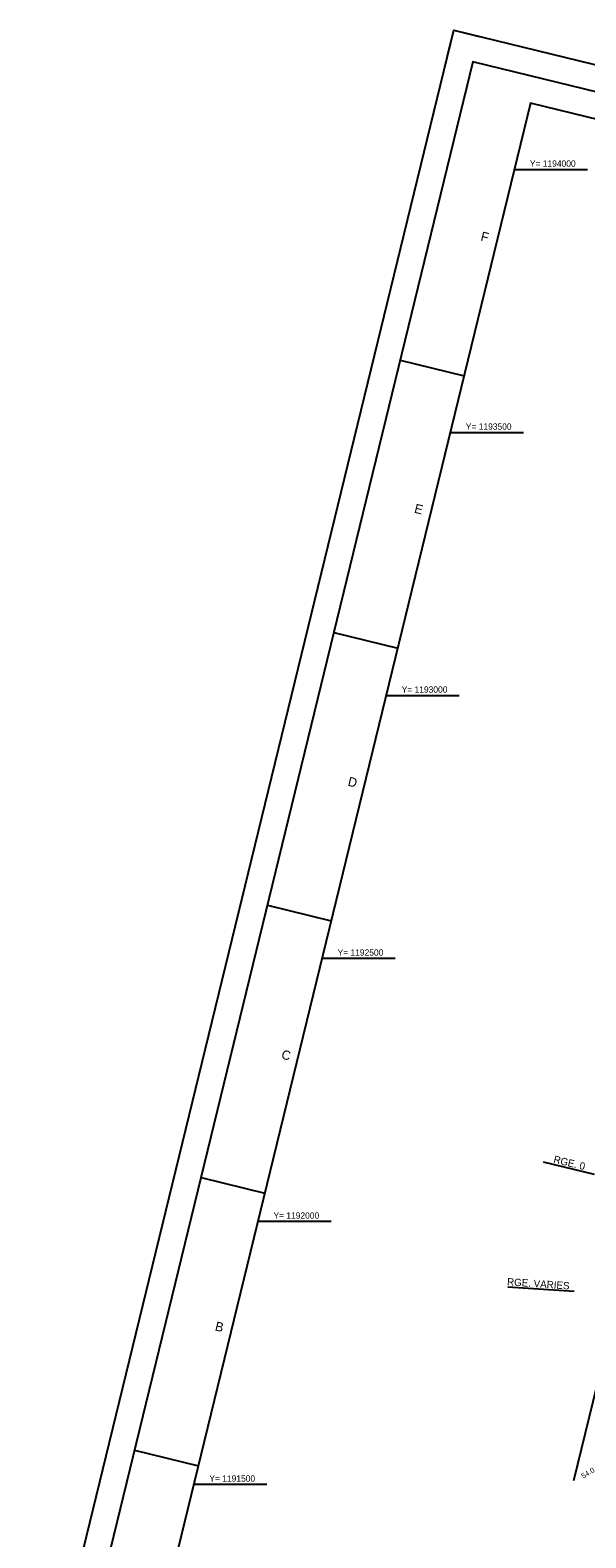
# Model space of a CAD drawing. Extents: x 403671 to 408751, y 1189919 to 1194265.
# Drawn here: x 403671 to 404728, y 1191398 to 1194265 of the extents above; entities that cross this region are included whole.
import ezdxf

# ---------------------------------------------------------------- set-up
doc = ezdxf.new("R2010")
doc.units = 0
for name, color, linetype in [('G-ANNO-NPLT', 7, 'Continuous'), ('G-ANNO-TTLB', 7, 'Continuous'), ('V-ALGN-TEXT', 7, 'Continuous'), ('V-ANNO-MATC', 7, 'Continuous'), ('V-TOPO-COOR-STAT', 7, 'Continuous'), ('V-TOPO-SOUN', 7, 'Continuous')]:
    doc.layers.add(name, color=color, linetype=linetype)

msp = doc.modelspace()

# ---------------------------------------------------------------- linework, layer by layer
at = {"layer": 'G-ANNO-NPLT'}
msp.add_lwpolyline([(404476.5, 1194264.7), (408751.2, 1193222.2), (407945.6, 1189919), (403670.9, 1190961.5)], close=True, dxfattribs=at)
msp.add_lwpolyline([(404464.6, 1194216.1), (404476.5, 1194264.7), (404525, 1194252.8)], dxfattribs=at)
at = {"layer": 'G-ANNO-TTLB'}
for p, q in [((404374.9, 1193637.4), (404496.4, 1193607.7)), ((404248.6, 1193119.2), (404370, 1193089.6)), ((404122.2, 1192601.1), (404243.7, 1192571.5)), ((403995.9, 1192083), (404117.3, 1192053.4)), ((403869.5, 1191564.9), (403991, 1191535.3))]:
    msp.add_line(p, q, dxfattribs=at)
for points in [[(403731.3, 1190998.2), (407908.9, 1189979.4), (408690.7, 1193185.4), (404513.2, 1194204.2)], [(408630.3, 1193148.7), (404622.8, 1194126), (403864.6, 1191017.2), (407872.1, 1190039.9)]]:
    msp.add_lwpolyline(points, close=True, dxfattribs=at)
at = {"layer": 'V-ALGN-TEXT'}
for p, q in [((404646.5, 1192113.4), (404743.7, 1192089.7)), ((404579.2, 1191875.4), (404705.4, 1191867))]:
    msp.add_line(p, q, dxfattribs=at)
at = {"layer": 'V-ANNO-MATC'}
msp.add_line((405089.6, 1193086.1), (404704.4, 1191506.3), dxfattribs=at)
at = {"layer": 'V-TOPO-COOR-STAT'}
for p, q in [((404592, 1194000), (404731, 1194000)), ((404470.1, 1193500), (404609.1, 1193500)), ((404348.2, 1193000), (404487.1, 1193000)), ((404226.2, 1192500), (404365.2, 1192500)), ((404104.3, 1192000), (404243.3, 1192000)), ((403982.4, 1191500), (404121.3, 1191500))]:
    msp.add_line(p, q, dxfattribs=at)

# ---------------------------------------------------------------- texts
at = {"layer": 'G-ANNO-TTLB'}
for s, p in [('F', (404526.7, 1193865)), ('E', (404400.4, 1193347.5)), ('D', (404274, 1192828.5)), ('C', (404147.6, 1192309.5)), ('B', (404021.4, 1191792.8))]:
    msp.add_text(s, height=17.5, rotation=346.2946, dxfattribs=at).set_placement(p)
at = {"layer": 'V-ALGN-TEXT'}
for s, rotation, p in [('RGE. 0', 346.2946, (404665.3, 1192111.7)), ('RGE. VARIES', 356.1651, (404577.7, 1191878.3))]:
    msp.add_text(s, height=13.92, rotation=rotation, dxfattribs=at).set_placement(p)
at = {"layer": 'V-TOPO-COOR-STAT'}
for s, p in [('Y= 1194000', (404621.5, 1194005)), ('Y= 1193500', (404499.6, 1193505)), ('Y= 1193000', (404377.6, 1193005)), ('Y= 1192500', (404255.7, 1192505)), ('Y= 1192000', (404133.7, 1192005)), ('Y= 1191500', (404011.8, 1191505))]:
    msp.add_text(s, height=12, dxfattribs=at).set_placement(p)
at = {"layer": 'V-TOPO-SOUN'}
msp.add_text('54.0 ', height=10, rotation=31.2939, dxfattribs=at).set_placement((404722.8, 1191510.3))

doc.saveas('drawing.dxf')
